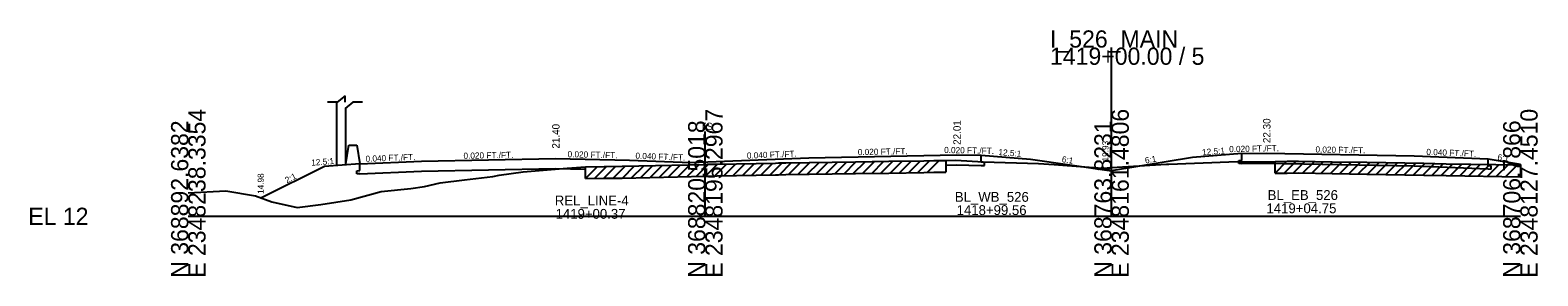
# Model space of a CAD drawing. Extents: x -170 to 2527928, y -10 to 1619750.
# Drawn here: x 3974.3 to 4219.3, y 490.3 to 530.3 of the extents above; entities that cross this region are included whole.
import ezdxf

# ---------------------------------------------------------------- set-up
doc = ezdxf.new("R2010")
doc.units = 0
for name, color, linetype in [('Default', 7, 'Continuous'), ('RD_GPK_XS_Cell', 7, 'Continuous'), ('RD_PD_NOISE-WALL-GM', 7, 'Continuous'), ('RD_XS_Base', 7, 'Continuous'), ('RD_XS_EarthShd', 7, 'Continuous'), ('RD_XS_ExGround', 7, 'Continuous'), ('RD_XS_ExPaveRet', 7, 'Continuous'), ('RD_XS_MatchLine', 7, 'Continuous'), ('RD_XS_Pave', 7, 'Continuous'), ('RD_XS_PaveShd', 7, 'Continuous'), ('RD_XS_TieSlope', 7, 'Continuous'), ('RD_XS_TX_Elev_EX', 7, 'Continuous'), ('RD_XS_TX_Slope', 7, 'Continuous'), ('RD_XS_TX_Station', 7, 'Continuous')]:
    doc.layers.add(name, color=color, linetype=linetype)

msp = doc.modelspace()

# ---------------------------------------------------------------- linework, layer by layer
at = {"layer": 'Default'}
for p, q in [((4025.46, 519.61), (4024.21, 518.58)), ((4025.46, 518.58), (4025.46, 519.61)), ((4024.21, 518.58), (4022.62, 518.58)), ((4026.71, 518.58), (4025.46, 517.55)), ((4028.3, 518.58), (4026.71, 518.58))]:
    msp.add_line(p, q, dxfattribs=at)
at = {"layer": 'RD_GPK_XS_Cell'}
for p, q in [((4150, 500), (4150, 527.45)), ((4000, 500), (4084, 500)), ((4084, 500), (4150, 500)), ((4150, 500), (4216.42, 500))]:
    msp.add_line(p, q, dxfattribs=at)
at = {"layer": 'RD_PD_NOISE-WALL-GM'}
for p, q in [((4024.08, 518.58), (4024.08, 508.26)), ((4025.58, 508.38), (4025.58, 517.65)), ((4025.58, 508.56), (4026.06, 511.56)), ((4026.06, 511.56), (4027.4, 511.56)), ((4027.4, 511.56), (4027.88, 508.56))]:
    msp.add_line(p, q, dxfattribs=at)
at = {"layer": 'RD_XS_Base'}
for p, q in [((4128.83, 508.79), (4128.83, 509.93)), ((4171.17, 509.09), (4171.17, 510.22)), ((4027.38, 507.41), (4027.88, 507.43)), ((4027.38, 506.91), (4027.38, 507.41)), ((4027.88, 507.43), (4027.88, 508.56)), ((4027.88, 506.93), (4037.88, 507.33)), ((4037.88, 507.33), (4059.67, 507.76)), ((4059.67, 507.76), (4064.53, 507.67)), ((4123.09, 508.34), (4124.83, 508.37)), ((4124.83, 508.37), (4128.83, 508.29)), ((4129.33, 508.78), (4128.83, 508.79)), ((4128.83, 508.29), (4129.33, 508.28)), ((4129.33, 508.28), (4129.33, 508.78)), ((4170.67, 509.08), (4171.17, 509.09)), ((4170.67, 508.58), (4170.67, 509.08)), ((4171.17, 508.59), (4170.67, 508.58)), ((4171.17, 508.59), (4175.17, 508.67)), ((4175.17, 508.67), (4199.17, 508.19)), ((4199.17, 508.19), (4211.17, 507.71)), ((4211.17, 508.21), (4211.17, 509.34)), ((4211.67, 508.19), (4211.17, 508.21)), ((4211.17, 507.71), (4211.67, 507.69)), ((4211.67, 507.69), (4211.67, 508.19)), ((4027.88, 506.93), (4027.38, 506.91))]:
    msp.add_line(p, q, dxfattribs=at)
at = {"layer": 'RD_XS_EarthShd'}
for p, q in [((4128.83, 509.93), (4136.83, 509.29)), ((4171.17, 510.22), (4163.17, 509.58)), ((4022.12, 508.1), (4011.87, 502.98)), ((4027.88, 508.56), (4022.12, 508.1))]:
    msp.add_line(p, q, dxfattribs=at)
at = {"layer": 'RD_XS_ExGround'}
msp.add_lwpolyline([(4000, 503.84), (4006.1, 504.13), (4010.9, 503.34), (4013.57, 502.35), (4017.71, 501.44), (4021.52, 501.94), (4026.38, 502.66), (4031.35, 504.02), (4036.14, 504.54), (4038.37, 504.86), (4040.94, 505.46), (4044.9, 505.94), (4049.49, 506.5), (4050.51, 506.68), (4054.43, 507.23), (4061.53, 507.83), (4064.53, 508.07), (4067.54, 508.11), (4070.51, 508.15), (4084, 508.45), (4084.32, 508.46), (4085.9, 508.49), (4095.4, 508.67), (4095.9, 508.68), (4097.08, 508.7), (4108.39, 508.86), (4113.8, 508.96), (4119.5, 509.05), (4121.15, 509.07), (4123.09, 509.1), (4124.7, 509.15), (4129.13, 508.89), (4138.15, 508.57), (4140.68, 508.45), (4145.65, 508.06), (4148.57, 507.83), (4150, 507.93), (4158.91, 508.49), (4159.06, 508.5), (4159.29, 508.51), (4169.03, 508.87), (4176.56, 508.94), (4178.52, 508.96), (4180.39, 508.98), (4185.82, 508.89), (4191.49, 508.79), (4200.76, 508.62), (4204.37, 508.56), (4216.42, 508.37)], dxfattribs=at)
at = {"layer": 'RD_XS_ExPaveRet'}
for p, q in [((4064.53, 506.15), (4066.47, 508.1)), ((4064.53, 506.15), (4064.53, 508.07)), ((4066.03, 506.18), (4067.97, 508.12)), ((4067.53, 506.2), (4069.46, 508.14)), ((4069.03, 506.22), (4070.97, 508.16)), ((4070.53, 506.23), (4072.49, 508.19)), ((4072.03, 506.27), (4073.99, 508.23)), ((4073.53, 506.3), (4075.49, 508.26)), ((4075.03, 506.33), (4076.99, 508.29)), ((4076.53, 506.37), (4078.49, 508.33)), ((4078.03, 506.4), (4079.99, 508.36)), ((4079.53, 506.43), (4081.49, 508.39)), ((4081.03, 506.47), (4082.99, 508.43)), ((4082.53, 506.5), (4084.49, 508.46)), ((4084.03, 506.53), (4085.99, 508.49)), ((4085.53, 506.57), (4087.48, 508.52)), ((4087.03, 506.6), (4088.98, 508.55)), ((4088.53, 506.62), (4090.48, 508.58)), ((4090.03, 506.65), (4091.98, 508.61)), ((4091.53, 506.68), (4093.48, 508.64)), ((4093.03, 506.71), (4094.98, 508.67)), ((4094.53, 506.74), (4096.48, 508.69)), ((4096.03, 506.77), (4097.97, 508.71)), ((4097.53, 506.79), (4099.47, 508.74)), ((4099.03, 506.81), (4100.97, 508.76)), ((4100.53, 506.83), (4102.47, 508.78)), ((4102.03, 506.86), (4103.97, 508.8)), ((4103.53, 506.88), (4105.47, 508.82)), ((4105.03, 506.9), (4106.97, 508.84)), ((4106.53, 506.92), (4108.47, 508.87)), ((4108.03, 506.94), (4109.97, 508.89)), ((4109.53, 506.97), (4111.47, 508.92)), ((4111.03, 506.99), (4112.97, 508.94)), ((4112.53, 507.02), (4114.47, 508.97)), ((4113.8, 507.04), (4119.5, 507.13)), ((4114.03, 507.04), (4115.97, 508.99)), ((4115.53, 507.07), (4117.47, 509.02)), ((4117.03, 507.09), (4118.97, 509.04)), ((4118.53, 507.12), (4120.47, 509.07)), ((4119.5, 507.13), (4121.15, 507.16)), ((4120.03, 507.14), (4121.97, 509.09)), ((4121.15, 507.16), (4123.09, 507.19)), ((4123.09, 509.1), (4123.09, 507.19)), ((4176.56, 507.02), (4178.5, 508.96)), ((4176.56, 507.02), (4176.56, 508.94)), ((4178.06, 507.03), (4180, 508.97)), ((4178.52, 507.04), (4180.39, 507.06)), ((4179.56, 507.05), (4181.47, 508.96)), ((4180.39, 507.06), (4185.82, 506.97)), ((4181.06, 507.05), (4182.95, 508.94)), ((4182.56, 507.03), (4184.45, 508.91)), ((4184.06, 507), (4185.95, 508.89)), ((4185.56, 506.98), (4187.45, 508.86)), ((4187.06, 506.95), (4188.95, 508.83)), ((4188.56, 506.92), (4190.45, 508.81)), ((4190.06, 506.9), (4191.95, 508.78)), ((4191.56, 506.87), (4193.45, 508.75)), ((4193.06, 506.84), (4194.95, 508.73)), ((4194.56, 506.82), (4196.45, 508.7)), ((4196.06, 506.79), (4197.95, 508.67)), ((4197.56, 506.76), (4199.45, 508.65)), ((4199.06, 506.74), (4200.95, 508.62)), ((4200.56, 506.71), (4202.45, 508.6)), ((4202.06, 506.69), (4203.95, 508.57)), ((4203.56, 506.66), (4205.45, 508.55)), ((4205.06, 506.64), (4206.95, 508.52)), ((4206.56, 506.61), (4208.45, 508.5)), ((4208.06, 506.59), (4209.95, 508.47)), ((4209.56, 506.56), (4211.45, 508.45)), ((4211.06, 506.54), (4212.95, 508.43)), ((4212.56, 506.52), (4214.45, 508.4)), ((4214.06, 506.49), (4215.95, 508.38)), ((4216.42, 508.37), (4216.42, 506.45)), ((4064.53, 506.15), (4067.54, 506.2)), ((4067.54, 506.2), (4070.51, 506.23)), ((4070.51, 506.23), (4084, 506.53)), ((4084, 506.53), (4084.32, 506.54)), ((4084.32, 506.54), (4085.9, 506.57)), ((4085.9, 506.57), (4095.4, 506.76)), ((4095.4, 506.76), (4095.9, 506.77)), ((4095.9, 506.77), (4097.08, 506.78)), ((4097.08, 506.78), (4108.39, 506.95)), ((4108.39, 506.95), (4113.8, 507.04)), ((4176.56, 507.02), (4178.52, 507.04)), ((4185.82, 506.97), (4191.49, 506.87)), ((4191.49, 506.87), (4200.76, 506.71)), ((4200.76, 506.71), (4204.37, 506.65)), ((4204.37, 506.65), (4216.42, 506.45))]:
    msp.add_line(p, q, dxfattribs=at)
at = {"layer": 'RD_XS_MatchLine'}
msp.add_line((4084, 500), (4084, 513.78), dxfattribs=at)
at = {"layer": 'RD_XS_Pave'}
for p, q in [((4100.83, 509.53), (4124.83, 510.01)), ((4175.17, 510.3), (4199.17, 509.82)), ((4037.88, 508.96), (4059.67, 509.4)), ((4059.67, 509.4), (4071.67, 509.16))]:
    msp.add_line(p, q, dxfattribs=at)
at = {"layer": 'RD_XS_PaveShd'}
for p, q in [((4081.66, 508.76), (4100.83, 509.53)), ((4124.83, 510.01), (4128.83, 509.93)), ((4171.17, 510.22), (4175.17, 510.3)), ((4199.17, 509.82), (4211.17, 509.34)), ((4027.88, 508.56), (4037.88, 508.96)), ((4071.67, 509.16), (4081.66, 508.76))]:
    msp.add_line(p, q, dxfattribs=at)
at = {"layer": 'RD_XS_TieSlope'}
for p, q in [((4163.17, 509.58), (4150, 507.39)), ((4136.83, 509.29), (4150, 507.39)), ((4211.17, 509.34), (4216.42, 508.47)), ((4216.42, 508.37), (4216.42, 508.47))]:
    msp.add_line(p, q, dxfattribs=at)

# ---------------------------------------------------------------- texts
at = {"layer": 'RD_GPK_XS_Cell'}
for s, p in [('I_526_MAIN', (4140, 527.45)), ('1419+00.00 / 5', (4140, 524.65)), ('EL 12', (3974, 498.6))]:
    msp.add_text(s, height=2.8, dxfattribs=at).set_placement(p)
for s, p in [('E 2348238.3354', (4002.8, 490)), ('E 2348195.2967', (4086.8, 490)), ('E 2348161.4806', (4152.8, 490)), ('E 2348127.4510', (4219.22, 490)), ('N 368892.6382', (4000, 490)), ('N 368820.5018', (4084, 490)), ('N 368763.8231', (4150, 490)), ('N 368706.7866', (4216.42, 490))]:
    msp.add_text(s, height=2.8, rotation=90, dxfattribs=at).set_placement(p)
at = {"layer": 'RD_XS_MatchLine'}
msp.add_text('TS', height=1.2, dxfattribs=at).set_placement((4083.14, 514.03))
at = {"layer": 'RD_XS_TX_Elev_EX'}
msp.add_text('19.93', height=1, rotation=90, dxfattribs=at).set_placement((4149.5, 508.93))
at = {"layer": 'RD_XS_TX_Slope'}
for s, rotation, p in [('12.5:1', 4.5739, (4020.01, 508.22)), ('0.040 FT./FT.', 2.2906, (4028.82, 508.85)), ('0.020 FT./FT.', 1.1458, (4044.72, 509.35)), ('0.020 FT./FT.', 358.8542, (4061.62, 509.61)), ('0.040 FT./FT.', 357.7094, (4072.63, 509.37)), ('0.040 FT./FT.', 2.2906, (4090.77, 509.37)), ('0.020 FT./FT.', 1.1458, (4108.78, 509.94)), ('0.020 FT./FT.', 358.8542, (4122.79, 510.3)), ('12.5:1', 355.4261, (4131.59, 509.97)), ('6:1', 350.5377, (4141.86, 508.83)), ('6:1', 9.4623, (4155.5, 508.59)), ('12.5:1', 4.5739, (4164.75, 509.92)), ('0.020 FT./FT.', 1.1458, (4169.11, 510.43)), ('0.020 FT./FT.', 358.8542, (4183.12, 510.39)), ('0.040 FT./FT.', 357.7094, (4201.13, 509.99)), ('6:1', 352.6182, (4212.66, 509.14)), ('14.98', 90, (4012.26, 503.64)), ('2:1', 26.5651, (4016.01, 505.35))]:
    msp.add_text(s, height=1, rotation=rotation, dxfattribs=at).set_placement(p)
at = {"layer": 'RD_XS_TX_Station'}
for s, p in [(' 21.40', (4060.32, 510.57)), (' 22.01', (4125.49, 511.18)), (' 22.30', (4175.82, 511.47))]:
    msp.add_text(s, height=1.2, rotation=90, dxfattribs=at).set_placement(p)
for s, p in [('REL_LINE-4', (4059.54, 501.77)), ('BL_WB_526', (4124.54, 502.36)), ('BL_EB_526', (4175.36, 502.66)), ('1419+00.37', (4059.67, 499.6)), ('1418+99.56', (4124.83, 500.21)), ('1419+04.75', (4175.17, 500.5))]:
    msp.add_text(s, height=1.6, dxfattribs=at).set_placement(p)

doc.saveas('drawing.dxf')
